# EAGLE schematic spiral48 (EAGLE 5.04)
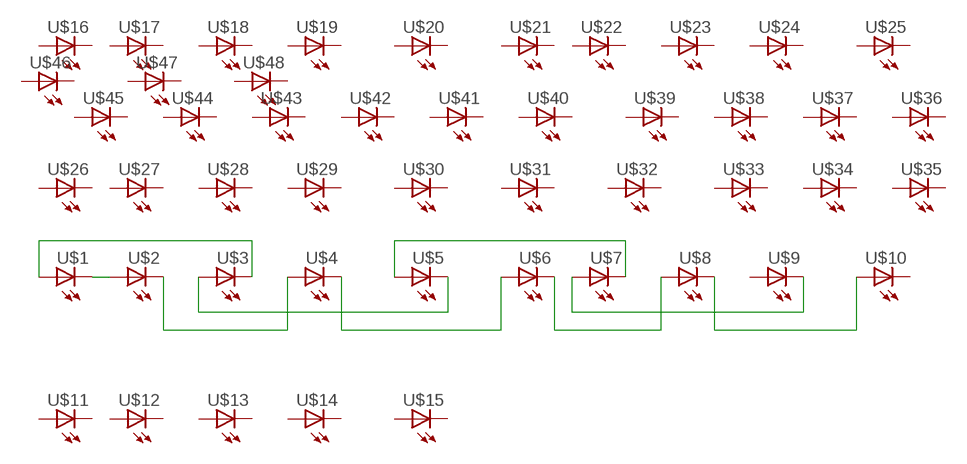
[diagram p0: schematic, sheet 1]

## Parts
U$1  LED5MM  [LED5MM]
U$2  LED5MM  [LED5MM]
U$3  LED5MM  [LED5MM]
U$4  LED5MM  [LED5MM]
U$5  LED5MM  [LED5MM]
U$6  LED5MM  [LED5MM]
U$7  LED5MM  [LED5MM]
U$8  LED5MM  [LED5MM]
U$9  LED5MM  [LED5MM]
U$10  LED5MM  [LED5MM]
U$11  LED5MM  [LED5MM]
U$12  LED5MM  [LED5MM]
U$13  LED5MM  [LED5MM]
U$14  LED5MM  [LED5MM]
U$15  LED5MM  [LED5MM]
U$16  LED5MM  [LED5MM]
U$17  LED5MM  [LED5MM]
U$18  LED5MM  [LED5MM]
U$19  LED5MM  [LED5MM]
U$20  LED5MM  [LED5MM]
U$21  LED5MM  [LED5MM]
U$22  LED5MM  [LED5MM]
U$23  LED5MM  [LED5MM]
U$24  LED5MM  [LED5MM]
U$25  LED5MM  [LED5MM]
U$26  LED5MM  [LED5MM]
U$27  LED5MM  [LED5MM]
U$28  LED5MM  [LED5MM]
U$29  LED5MM  [LED5MM]
U$30  LED5MM  [LED5MM]
U$31  LED5MM  [LED5MM]
U$32  LED5MM  [LED5MM]
U$33  LED5MM  [LED5MM]
U$34  LED5MM  [LED5MM]
U$35  LED5MM  [LED5MM]
U$36  LED5MM  [LED5MM]
U$37  LED5MM  [LED5MM]
U$38  LED5MM  [LED5MM]
U$39  LED5MM  [LED5MM]
U$40  LED5MM  [LED5MM]
U$41  LED5MM  [LED5MM]
U$42  LED5MM  [LED5MM]
U$43  LED5MM  [LED5MM]
U$44  LED5MM  [LED5MM]
U$45  LED5MM  [LED5MM]
U$46  LED5MM  [LED5MM]
U$47  LED5MM  [LED5MM]
U$48  LED5MM  [LED5MM]

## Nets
N$1: U$1.K(C) U$2.A
N$2: U$2.K(C) U$4.A
N$3: U$4.K(C) U$6.A
N$4: U$6.K(C) U$8.A
N$5: U$8.K(C) U$10.A
N$6: U$1.A U$3.K(C)
N$7: U$3.A U$5.K(C)
N$8: U$5.A U$7.K(C)
N$9: U$7.A U$9.K(C)
Unconnected: U$9.A U$10.K(C) U$11.A U$11.K(C) U$12.A U$12.K(C) U$13.A U$13.K(C) U$14.A U$14.K(C) U$15.A U$15.K(C) U$16.A U$16.K(C) U$17.A U$17.K(C) U$18.A U$18.K(C) U$19.A U$19.K(C) U$20.A U$20.K(C) U$21.A U$21.K(C) U$22.A U$22.K(C) U$23.A U$23.K(C) U$24.A U$24.K(C) U$25.A U$25.K(C) U$26.A U$26.K(C) U$27.A U$27.K(C) U$28.A U$28.K(C) U$29.A U$29.K(C) U$30.A U$30.K(C) U$31.A U$31.K(C) U$32.A U$32.K(C) U$33.A U$33.K(C) U$34.A U$34.K(C) U$35.A U$35.K(C) U$36.A U$36.K(C) U$37.A U$37.K(C) U$38.A U$38.K(C) U$39.A U$39.K(C) U$40.A U$40.K(C) U$41.A U$41.K(C) U$42.A U$42.K(C) U$43.A U$43.K(C) U$44.A U$44.K(C) U$45.A U$45.K(C) U$46.A U$46.K(C) U$47.A U$47.K(C) U$48.A U$48.K(C)

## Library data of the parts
U$1-U$48 = led(2):LED: LED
